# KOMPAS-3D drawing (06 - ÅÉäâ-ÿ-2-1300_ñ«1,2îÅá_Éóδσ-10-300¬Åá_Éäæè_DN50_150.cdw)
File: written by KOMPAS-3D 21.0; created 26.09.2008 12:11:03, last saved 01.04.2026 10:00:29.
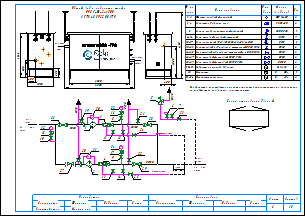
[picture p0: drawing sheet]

Sheets 1-2: A3, landscape

Document properties: Наименование: Макро:21; Автор: RaskoAdmin; Форматы листов документа: 2xA3; Полное имя файла: \\UR38nt01\Departments\КТО\КБ ПУРДГ\Заявки\Прайс-лист на типовые шкафы ГРПШ\ПРДГ_стандарт_20_03_2026\ПРДГ с РДСК\ПРДГ-Ш-2-1300_до1,2МПа_Рвых-10-300кПа_РДСК_DN50_150.cdw

Title block, sheet 1: Наименование: Пункт учета газа / ПУГ-Ш-400-Р / ЛГТИ.485922.001ТУ; designation: ЛГТИ.03.4411141; sheet number: 1; Количество листов документа: 2; organisation: ООО "ЭЛЬСТЕР Газэлектроника"; Форматы листов документа: A3; stored path: C:\Рабочие документы\Компас\ПУГ\Схема.cdw; Разработал: Устинов; Проверил: Кошкин; Утвердил: Кошкин
Title block, sheet 2: sheet number: 2; stored path: D:\Рабочие документы\Заявки\ПУРДГ\ПУРДГ-ШУЭО-2-100-Р 4411220.cdw; designation, second copy: ЛГТИ.03.4411141-

Views: Вид 1, Вид 2
Referenced files: wcvoit.frw
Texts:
  Normal
  Вход
  газа
  PDI
  Выход
  Р=     кПа
  DN150
  DN50
  DN20
  Импульс DN20
  ≥5DN
  HYSWLongFangSong
  № на
  схеме
  Усл.
  обозн.
  Марка
  (модель)
  Кол.
  Фильтр газовый фланцевый
  ФГ 16-50
  Регулятор давления газа
  РДCК-50
  Клапан предохранительный сбросной
  КПС DN20
  Кран шаровой газовый латунный
  DN15
  Кран кнопочный VE-РАСКО-НЗ-1,6-G1/2-М20
  Кран шаровой "под приварку" штуцерный DN20 PN16
  Кран шаровой "под приварку" штуцерный п/п DN20 PN16
  Кран шаровой фланцевый DN50 PN16
  Кран шаровой фланцевый DN150 PN16
  Индикатор перепада давления
  Delta 15
  Манометр
  Манометр-напоромер
  0...     МПа
  0...     кПа
  Общий вид и габариты шкафа
  ПРДГ-Ш-2-1300
  Выход газа
  Вход газа
  Схема открывания дверей
  Р=        МПа
  logo-rasko-ge.png
  Предприятие изготовитель может заменять комплектующие на аналогичные,
  не ухудшающие заявленных характеристик.
  Должность
  Конструктор
  Фамилия
  Подпись
  Дата
  Согласовано
  Максимкин
  Лист
  Листов
  POLYLINE_STYLE_0.18_RGB_0_0_0
  POLYLINE_STYLE_0.50_RGB_0_0_0
  POLYLINE_STYLE_0.34_RGB_0_0_0
  PHANTOM_RGB_0_0_0_SC_1_THICK_0.18
  K5LT_THIN_RGB_0_0_0_THICK_0.18
  K5LT32769_RGB_0_0_0_THICK_0.18
  K5LT12_RGB_0_0_0_SC_1_THICK_0.18
  K5LT_DASHED_RGB_0_0_0_SC_1_THICK_0.18
  ACISOTGL_RGB_0_0_0_SC_0.8_THICK_0.25
  CONTINUOUS_RGB_0_127_31_THICK_0.3
  CONTINUOUS_RGB_0_0_255_THICK_0.35
  CONTINUOUS_RGB_255_0_0_THICK_0.35
  POLYLINE_STYLE_0.25_RGB_0_0_0
  CONTINUOUS_RGB_0_0_0_THICK_0.5
  POLYLINE_STYLE_0.35_RGB_0_0_255
  CONTINUOUS_RGB_0_0_0_THICK_0.4
  CONTINUOUS_RGB_0_0_0_THICK_0.35
  Без оформления
Dimensions and other numbers on the sheet: 1; 2; 3; 4; 5; 10; 27; 28; 29; 23; 8; 12; 19; 20; 21; 22; 25; 24; 30; 31; 15; 16; 26; 6; 7; 11; 14; 13; 33; 1, 2; 3, 4; 6-14; 9; 15-17; 18-23; 24-25; 26-27; 28-29; 30-31; 32; 33-34; 400; 1050; 500; 305; 2500; 1565; 2800; 17; 34; 1000; 4130; 18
